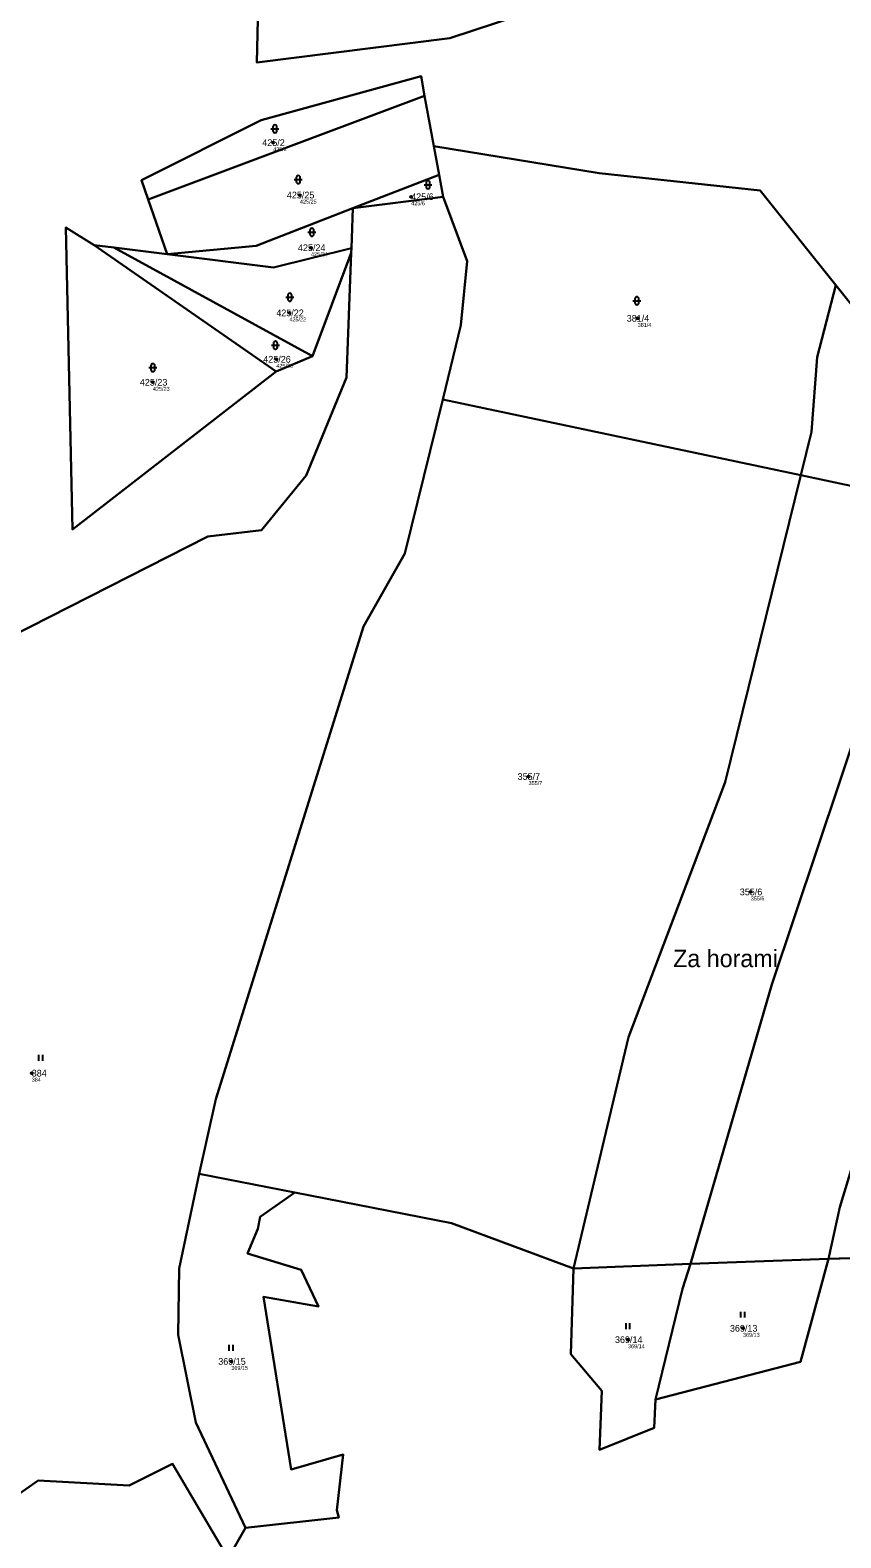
# Model space of a CAD drawing. Extents: x -767985 to -763816, y -1059600 to -1057360.
# Drawn here: x -765772.9 to -765567.9, y -1058237.1 to -1057855.6 of the extents above; entities that cross this region are included whole.
import ezdxf

# ---------------------------------------------------------------- set-up
doc = ezdxf.new("R2010")
doc.units = 0
for name, color, linetype in [('Definiční body', 7, 'Continuous'), ('Hranice parcel', 7, 'Continuous'), ('Parcelní čísla', 7, 'Continuous'), ('Polygon parcely', 7, 'Continuous'), ('Pop  PČ popisy', 7, 'Continuous'), ('Značky kultur', 7, 'Continuous')]:
    doc.layers.add(name, color=color, linetype=linetype)

msp = doc.modelspace()

# ---------------------------------------------------------------- linework, layer by layer
at = {"layer": 'Definiční body'}
for centre in [(-765711.42, -1057884.04994), (-765704.67, -1057897.31994), (-765676.53, -1057897.73994), (-765701.87, -1057910.63994), (-765707.34, -1057927.12994), (-765619.24, -1057928.50994), (-765710.64, -1057938.86994), (-765741.85, -1057944.68994), (-765646.84, -1058044.45994), (-765590.65, -1058073.64994), (-765772.5, -1058119.51994), (-765592.61, -1058184.06994), (-765621.69, -1058186.95994), (-765722.02, -1058192.45994)]:
    msp.add_circle(centre, 0.25, dxfattribs=at)
at = {"layer": 'Hranice parcel'}
for p, q in [((-765743.07, -1057898.45), (-765673.13, -1057872.22)), ((-765673.13, -1057872.22), (-765670.79, -1057884.95)), ((-765670.79, -1057884.95), (-765669.46, -1057892.19)), ((-765669.46, -1057892.19), (-765691.29, -1057900.67)), ((-765668.44, -1057897.76), (-765669.46, -1057892.19)), ((-765738.25, -1057912.3), (-765743.07, -1057898.45)), ((-765668.44, -1057897.76), (-765691.29, -1057900.67)), ((-765691.29, -1057900.67), (-765691.67, -1057910.77)), ((-765756.67, -1057909.96), (-765751.7, -1057910.59)), ((-765710.66, -1057941.95), (-765756.67, -1057909.96)), ((-765751.7, -1057910.59), (-765738.25, -1057912.3)), ((-765751.7, -1057910.59), (-765701.51, -1057938.05)), ((-765691.71, -1057911.92), (-765701.51, -1057938.05)), ((-765691.67, -1057910.77), (-765691.71, -1057911.92)), ((-765701.51, -1057938.05), (-765710.66, -1057941.95)), ((-765577.98, -1057968.23), (-765668.56, -1057949.03)), ((-765546.75, -1057974.85), (-765577.98, -1057968.23)), ((-765730.15, -1058144.98), (-765705.97, -1058149.71)), ((-765605.93, -1058167.78), (-765570.95, -1058166.5)), ((-765570.95, -1058166.5), (-765557.31, -1058166.07)), ((-765635.5, -1058168.98), (-765605.93, -1058167.78))]:
    msp.add_line(p, q, dxfattribs=at)
for points in [[(-765649.04, -1057851.8), (-765666.77, -1057857.64), (-765715.58, -1057863.75), (-765714.78, -1057831.07)], [(-765673.13, -1057872.22), (-765674.05, -1057867.21), (-765714.45, -1057878.35), (-765744.78, -1057893.52), (-765743.07, -1057898.45)], [(-765670.79, -1057884.95), (-765628.96, -1057891.78), (-765588.23, -1057896.17), (-765569.13, -1057920.09)], [(-765668.56, -1057949.03), (-765663.97, -1057930.24), (-765662.37, -1057914.02), (-765668.44, -1057897.76)], [(-765691.29, -1057900.67), (-765715.78, -1057910.18), (-765738.25, -1057912.3)], [(-765710.66, -1057941.95), (-765762.18, -1057981.92), (-765763.9, -1057905.55), (-765756.67, -1057909.96)], [(-765691.71, -1057911.92), (-765692.87, -1057943.48), (-765703.08, -1057968.27), (-765714.39, -1057982.08), (-765727.95, -1057983.75), (-765788.09, -1058014.28)], [(-765691.67, -1057910.77), (-765711.39, -1057915.65), (-765738.25, -1057912.3)], [(-765569.13, -1057920.09), (-765573.82, -1057938.3), (-765575.27, -1057957.22), (-765577.98, -1057968.23)], [(-765569.13, -1057920.09), (-765555.93, -1057936.62), (-765538.49, -1057943.77)], [(-765730.15, -1058144.98), (-765725.97, -1058126.07), (-765688.61, -1058006.48), (-765678.1, -1057988.03), (-765668.56, -1057949.03)], [(-765577.98, -1057968.23), (-765597.08, -1058045.92), (-765621.56, -1058110.38), (-765635.5, -1058168.98)], [(-765546.75, -1057974.85), (-765554.2, -1058001.07), (-765556.65, -1058011.49), (-765585.32, -1058097.06), (-765605.93, -1058167.78)], [(-765570.95, -1058166.5), (-765568.15, -1058153.4), (-765562.94, -1058136.5)], [(-765718.45, -1058234.57), (-765730.96, -1058207.91), (-765735.45, -1058185.77), (-765735.21, -1058168.95), (-765730.15, -1058144.98)], [(-765705.97, -1058149.71), (-765714.76, -1058155.88), (-765715.35, -1058158.88), (-765717.97, -1058165.17), (-765704.32, -1058169.27), (-765699.97, -1058178.53), (-765713.91, -1058176.08), (-765706.9, -1058219.79), (-765693.71, -1058215.98), (-765695.32, -1058230.1), (-765694.81, -1058231.96), (-765718.45, -1058234.57)], [(-765705.97, -1058149.71), (-765666.3, -1058157.48), (-765635.5, -1058168.98)], [(-765570.95, -1058166.5), (-765578.1, -1058192.55), (-765614.72, -1058202.07)], [(-765614.72, -1058202.07), (-765615.05, -1058209.28), (-765628.89, -1058214.85), (-765628.32, -1058199.93), (-765636.18, -1058190.59), (-765635.5, -1058168.98)], [(-765605.93, -1058167.78), (-765607.93, -1058174.13), (-765614.72, -1058202.07)], [(-765842.81, -1058253.81), (-765831.83, -1058255.4), (-765808.35, -1058247.02), (-765806.35, -1058235.67), (-765783.41, -1058231.37), (-765770.89, -1058222.6), (-765747.89, -1058223.85), (-765736.9, -1058218.35), (-765722.84, -1058242.26), (-765718.45, -1058234.57)]]:
    msp.add_lwpolyline(points, dxfattribs=at)
at = {"layer": 'Polygon parcely'}
for points in [[(-765649.04, -1057851.8), (-765659.8, -1057831.35), (-765714.78, -1057831.07), (-765715.58, -1057863.75), (-765666.77, -1057857.64)], [(-765743.07, -1057898.45), (-765673.13, -1057872.22), (-765674.05, -1057867.21), (-765714.45, -1057878.35), (-765744.78, -1057893.52)], [(-765673.13, -1057872.22), (-765743.07, -1057898.45), (-765738.25, -1057912.3), (-765715.78, -1057910.18), (-765691.29, -1057900.67), (-765669.46, -1057892.19), (-765670.79, -1057884.95)], [(-765670.79, -1057884.95), (-765669.46, -1057892.19), (-765668.44, -1057897.76), (-765662.37, -1057914.02), (-765663.97, -1057930.24), (-765668.56, -1057949.03), (-765577.98, -1057968.23), (-765575.27, -1057957.22), (-765573.82, -1057938.3), (-765569.13, -1057920.09), (-765588.23, -1057896.17), (-765628.96, -1057891.78)], [(-765669.46, -1057892.19), (-765691.29, -1057900.67), (-765668.44, -1057897.76)], [(-765738.25, -1057912.3), (-765711.39, -1057915.65), (-765691.67, -1057910.77), (-765691.29, -1057900.67), (-765715.78, -1057910.18)], [(-765710.66, -1057941.95), (-765756.67, -1057909.96), (-765763.9, -1057905.55), (-765762.18, -1057981.92)], [(-765710.66, -1057941.95), (-765701.51, -1057938.05), (-765751.7, -1057910.59), (-765756.67, -1057909.96)], [(-765711.39, -1057915.65), (-765738.25, -1057912.3), (-765751.7, -1057910.59), (-765701.51, -1057938.05), (-765691.71, -1057911.92), (-765691.67, -1057910.77)], [(-765573.82, -1057938.3), (-765575.27, -1057957.22), (-765577.98, -1057968.23), (-765546.75, -1057974.85), (-765538.49, -1057943.77), (-765555.93, -1057936.62), (-765569.13, -1057920.09)], [(-765730.15, -1058144.98), (-765705.97, -1058149.71), (-765666.3, -1058157.48), (-765635.5, -1058168.98), (-765621.56, -1058110.38), (-765597.08, -1058045.92), (-765577.98, -1057968.23), (-765668.56, -1057949.03), (-765678.1, -1057988.03), (-765688.61, -1058006.48), (-765725.97, -1058126.07)], [(-765597.08, -1058045.92), (-765621.56, -1058110.38), (-765635.5, -1058168.98), (-765605.93, -1058167.78), (-765585.32, -1058097.06), (-765556.65, -1058011.49), (-765554.2, -1058001.07), (-765546.75, -1057974.85), (-765577.98, -1057968.23)], [(-765605.93, -1058167.78), (-765570.95, -1058166.5), (-765568.15, -1058153.4), (-765562.94, -1058136.5), (-765535.65, -1058049.29), (-765523.79, -1058005.07), (-765522.24, -1057980.05), (-765546.75, -1057974.85), (-765554.2, -1058001.07), (-765556.65, -1058011.49), (-765585.32, -1058097.06)], [(-765570.95, -1058166.5), (-765557.31, -1058166.07), (-765562.94, -1058136.5), (-765568.15, -1058153.4)], [(-765730.15, -1058144.98), (-765735.21, -1058168.95), (-765735.45, -1058185.77), (-765730.96, -1058207.91), (-765718.45, -1058234.57), (-765694.81, -1058231.96), (-765695.32, -1058230.1), (-765693.71, -1058215.98), (-765706.9, -1058219.79), (-765713.91, -1058176.08), (-765699.97, -1058178.53), (-765704.32, -1058169.27), (-765717.97, -1058165.17), (-765715.35, -1058158.88), (-765714.76, -1058155.88), (-765705.97, -1058149.71)], [(-765614.72, -1058202.07), (-765578.1, -1058192.55), (-765570.95, -1058166.5), (-765605.93, -1058167.78), (-765607.93, -1058174.13)], [(-765605.93, -1058167.78), (-765635.5, -1058168.98), (-765636.18, -1058190.59), (-765628.32, -1058199.93), (-765628.89, -1058214.85), (-765615.05, -1058209.28), (-765614.72, -1058202.07), (-765607.93, -1058174.13)]]:
    msp.add_lwpolyline(points, close=True, dxfattribs=at)
for points in [[(-765649.04, -1057851.8), (-765666.77, -1057857.64), (-765715.58, -1057863.75), (-765714.78, -1057831.07)], [(-765788.09, -1058014.28), (-765727.95, -1057983.75), (-765714.39, -1057982.08), (-765703.08, -1057968.27), (-765692.87, -1057943.48), (-765691.71, -1057911.92), (-765701.51, -1057938.05), (-765710.66, -1057941.95), (-765762.18, -1057981.92), (-765763.9, -1057905.55), (-765756.67, -1057909.96), (-765751.7, -1057910.59), (-765738.25, -1057912.3), (-765743.07, -1057898.45), (-765744.78, -1057893.52), (-765714.45, -1057878.35), (-765674.05, -1057867.21), (-765673.13, -1057872.22), (-765670.79, -1057884.95), (-765628.96, -1057891.78), (-765588.23, -1057896.17), (-765569.13, -1057920.09), (-765555.93, -1057936.62)], [(-765783.41, -1058231.37), (-765770.89, -1058222.6), (-765747.89, -1058223.85), (-765736.9, -1058218.35), (-765722.84, -1058242.26), (-765718.45, -1058234.57), (-765730.96, -1058207.91), (-765735.45, -1058185.77), (-765735.21, -1058168.95), (-765730.15, -1058144.98), (-765725.97, -1058126.07), (-765688.61, -1058006.48), (-765678.1, -1057988.03), (-765668.56, -1057949.03), (-765663.97, -1057930.24), (-765662.37, -1057914.02), (-765668.44, -1057897.76), (-765691.29, -1057900.67), (-765691.67, -1057910.77), (-765691.71, -1057911.92), (-765692.87, -1057943.48), (-765703.08, -1057968.27), (-765714.39, -1057982.08), (-765727.95, -1057983.75), (-765788.09, -1058014.28)], [(-765557.31, -1058166.07), (-765570.95, -1058166.5), (-765578.1, -1058192.55), (-765614.72, -1058202.07), (-765615.05, -1058209.28), (-765628.89, -1058214.85), (-765628.32, -1058199.93), (-765636.18, -1058190.59), (-765635.5, -1058168.98), (-765666.3, -1058157.48), (-765705.97, -1058149.71), (-765714.76, -1058155.88), (-765715.35, -1058158.88), (-765717.97, -1058165.17), (-765704.32, -1058169.27), (-765699.97, -1058178.53), (-765713.91, -1058176.08), (-765706.9, -1058219.79), (-765693.71, -1058215.98), (-765695.32, -1058230.1), (-765694.81, -1058231.96), (-765718.45, -1058234.57), (-765722.84, -1058242.26), (-765736.9, -1058218.35), (-765747.89, -1058223.85), (-765770.89, -1058222.6), (-765783.41, -1058231.37)]]:
    msp.add_lwpolyline(points, dxfattribs=at)
at = {"layer": 'Značky kultur'}
for p, q in [((-765711.991, -1057880.561), (-765709.989, -1057880.561)), ((-765711.491, -1057880.061), (-765711.491, -1057881.062)), ((-765710.489, -1057881.062), (-765710.489, -1057880.061)), ((-765706.101, -1057893.411), (-765704.099, -1057893.411)), ((-765705.601, -1057892.911), (-765705.601, -1057893.912)), ((-765704.599, -1057893.912), (-765704.599, -1057892.911)), ((-765673.281, -1057894.701), (-765671.279, -1057894.701)), ((-765672.781, -1057894.201), (-765672.781, -1057895.202)), ((-765671.779, -1057895.202), (-765671.779, -1057894.201)), ((-765702.651, -1057906.721), (-765700.649, -1057906.721)), ((-765702.151, -1057906.221), (-765702.151, -1057907.222)), ((-765701.149, -1057907.222), (-765701.149, -1057906.221)), ((-765708.231, -1057923.171), (-765706.229, -1057923.171)), ((-765707.731, -1057922.671), (-765707.731, -1057923.672)), ((-765706.729, -1057923.672), (-765706.729, -1057922.671)), ((-765620.451, -1057924.071), (-765618.449, -1057924.071)), ((-765619.951, -1057923.571), (-765619.951, -1057924.572)), ((-765618.949, -1057924.572), (-765618.949, -1057923.571)), ((-765711.361, -1057934.831), (-765711.361, -1057935.832)), ((-765710.359, -1057935.832), (-765710.359, -1057934.831)), ((-765711.861, -1057935.331), (-765709.859, -1057935.331)), ((-765742.851, -1057940.991), (-765740.849, -1057940.991)), ((-765742.351, -1057940.491), (-765742.351, -1057941.492)), ((-765741.349, -1057941.492), (-765741.349, -1057940.491)), ((-765770.701, -1058116.4), (-765770.701, -1058114.9)), ((-765769.7, -1058116.4), (-765769.7, -1058114.9)), ((-765622.201, -1058184.26), (-765622.201, -1058182.76)), ((-765621.2, -1058184.26), (-765621.2, -1058182.76)), ((-765593.121, -1058181.37), (-765593.121, -1058179.87)), ((-765592.12, -1058181.37), (-765592.12, -1058179.87)), ((-765722.531, -1058189.76), (-765722.531, -1058188.26)), ((-765721.53, -1058189.76), (-765721.53, -1058188.26))]:
    msp.add_line(p, q, dxfattribs=at)
for centre, start, end in [((-765710.99, -1057880.0609), 0, 180), ((-765710.99, -1057881.0609), 180, 359.9878861), ((-765705.1, -1057892.9109), 0, 180), ((-765705.1, -1057893.9109), 180, 359.9878861), ((-765672.28, -1057894.2009), 0, 180), ((-765672.28, -1057895.2009), 180, 359.9878861), ((-765701.65, -1057906.2209), 0, 180), ((-765701.65, -1057907.2209), 180, 359.9878861), ((-765707.23, -1057922.6709), 0, 180), ((-765619.45, -1057923.5709), 0, 180), ((-765707.23, -1057923.6709), 180, 359.9878861), ((-765619.45, -1057924.5709), 180, 359.9878861), ((-765710.86, -1057934.8309), 0, 180), ((-765710.86, -1057935.8309), 180, 359.9878861), ((-765741.85, -1057940.4909), 0, 180), ((-765741.85, -1057941.4909), 180, 359.9878861)]:
    msp.add_arc(centre, 0.5, start, end, dxfattribs=at)

# ---------------------------------------------------------------- texts
at = {"layer": 'Definiční body'}
for s, p in [('425/2', (-765711.42, -1057886.206)), ('425/25', (-765704.67, -1057899.476)), ('425/6', (-765676.53, -1057899.896)), ('425/24', (-765701.87, -1057912.796)), ('425/22', (-765707.34, -1057929.286)), ('381/4', (-765619.24, -1057930.666)), ('425/26', (-765710.64, -1057941.026)), ('425/23', (-765741.85, -1057946.846)), ('355/7', (-765646.84, -1058046.616)), ('355/6', (-765590.65, -1058075.806)), ('384', (-765772.5, -1058121.676)), ('369/13', (-765592.61, -1058186.226)), ('369/14', (-765621.69, -1058189.116)), ('369/15', (-765722.02, -1058194.616))]:
    msp.add_text(s, height=0.999996, dxfattribs=at).set_placement(p)
at = {"layer": 'Parcelní čísla'}
for s, p in [('425/2', (-765714.193, -1057884.9)), ('425/25', (-765707.975, -1057898.17)), ('425/6', (-765676.53, -1057898.59)), ('425/24', (-765705.175, -1057911.49)), ('425/22', (-765710.645, -1057927.98)), ('381/4', (-765622.013, -1057929.36)), ('425/26', (-765713.945, -1057939.72)), ('425/23', (-765745.155, -1057945.54)), ('355/7', (-765649.613, -1058045.31)), ('355/6', (-765593.423, -1058074.5)), ('384', (-765772.5, -1058120.37)), ('369/14', (-765624.995, -1058187.81)), ('369/13', (-765595.915, -1058184.92)), ('369/15', (-765725.325, -1058193.31))]:
    msp.add_text(s, height=1.699998, dxfattribs=at).set_placement(p)
at = {"layer": 'Pop  PČ popisy'}
msp.add_text('Za horami', height=4.399998, dxfattribs=at).set_placement((-765610.28, -1058092.69))

doc.saveas('drawing.dxf')
